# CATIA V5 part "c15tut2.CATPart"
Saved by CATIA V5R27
Part number: Part1
Bounding box of the stored display mesh (mm): x -53 to 53, y -20 to 21, z -12 to 52
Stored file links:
  E:\_Deepak\2017_Deepak\CATIA\Resources\Tutorial Files\Tutorials\c15_catia_v5_6r2016_tut\c15tut2.CATPart
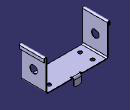
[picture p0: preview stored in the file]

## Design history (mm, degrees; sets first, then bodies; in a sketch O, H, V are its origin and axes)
SheetMetalParameters1: Thickness 1, BendRadius 2, KFactor 0.400515 {= log(min(100,max(20*SheetMetalParameters1.BendRadius,SheetMetalParameters1.Thickness)/SheetMetalParameters1.Thickness))/log(100)/2}, ReliefRadialLength 1, ReliefAxialLength 2, MinimumBendRadius 0
Body1 (main body)
  Sketch1 on xy-plane, origin (0, 0, 0), H (1, 0, 0), V (0, 1, 0)
    line L1 (50, 20) -> (50, -20)
    line L2 (50, -20) -> (-50, -20)
    line L3 (-50, -20) -> (-50, 20)
    line L4 (-50, 20) -> (50, 20)
    length L4 = 100
    length L1 = 40
    vertical: L1 V, L3 V
    horizontal: L2 H, L4 H
    equidistance: L1 L3 O, L2 L4 O
  Wall1: Thickness 1, Profile Sketch1
  Sketch2 on face of Wall1, origin (29.2419, -0.5458, 1), H (1, 0, 0), V (0, 1, 0)
    point P1 (-64.2419, -9.4542)
    reference projected line E1 (-79.2419, -19.4542) -> (-79.2419, 20.5458) from edge [face of Wall1 | face of Wall1]
    reference projected line E2 (20.7581, -19.4542) -> (-79.2419, -19.4542) from edge [face of Wall1 | face of Wall1]
    distance E1 P1 = 15
    distance E2 P1 = 10
  Hole1: placed by Sketch2, at (-35, -10, 1) direction (0, 0, -1), diameter 6, depth 10
  RectPattern1: of Hole1, direction 1 instances 2, spacing 70, along edge [face of Wall1 | face of Wall1] reversed, direction 2 instances 2, spacing 20, along edge [face of Wall1 | face of Wall1]
  Flange1: Angle 90, Length 50, Radius 2, KFacteur 0.400515 {= log(min(100,max(20*Flange1.Radius,SheetMetalParameters1.Thickness)/SheetMetalParameters1.Thickness))/log(100)/2}, Guide edge [face of Wall1 | face of Wall1]
  Flange2: Angle 90, Length 50, Radius 2, KFacteur 0.400515 {= log(min(100,max(20*Flange2.Radius,SheetMetalParameters1.Thickness)/SheetMetalParameters1.Thickness))/log(100)/2}, Guide edge [face of Wall1 | face of Wall1]
  Flange3: Angle 90, Length 5, Radius 1, KFacteur 0.325257 {= log(min(100,max(20*Flange3.Radius,SheetMetalParameters1.Thickness)/SheetMetalParameters1.Thickness))/log(100)/2}, Guide edge [face of Flange2 | face of Flange2]
  Flange4: Angle 90, Length 5, Radius 1, KFacteur 0.325257 {= log(min(100,max(20*Flange4.Radius,SheetMetalParameters1.Thickness)/SheetMetalParameters1.Thickness))/log(100)/2}, Guide edge [face of Flange1 | face of Flange1]
  Sketch3 on face of Flange1, origin (50, 0, 0), H (0, 1, 0), V (0, 0, 1)
    arc A1 centre (0, 25) radius 6 from (-1, 30.9161) to (1, 30.9161) ccw
    point P1 (0, 25)
    line L1 (-1, 30.9161) -> (-1, 29.9161)
    line L2 (-1, 29.9161) -> (1, 29.9161)
    line L3 (1, 29.9161) -> (1, 30.9161)
    radius A1 = 6
    distance H P1 = 25
    length L2 = 2
    distance V L1 = 1
    length L3 = 1
    coincidence: P1 V
    vertical: L1 V, L3 V
    horizontal: L2 H
  CutOut1: Direction Sketch3, EndLimit through (limit type 3), Orientation true, Profile Sketch3, StartLimit through (limit type 2)
  d_NewWallOnEdge1: NewWallOnEdge_Edge edge [face of Wall1 | face of Wall1], NewWallOnEdge_Length 13, NewWallOnEdge_HeightLimitOffset 0, NewWallOnEdge_WidthOffset1 -41, NewWallOnEdge_WidthOffset2 -41, NewWallOnEdge_Angle 90, NewWallOnEdge_BendRadiusValue 2 {= SheetMetalParameters1.BendRadius}, KFacteur 0.400515 {= log(min(100,max(20*d_NewWallOnEdge1.Radius,SheetMetalParameters1.Thickness)/SheetMetalParameters1.Thickness))/log(100)/2}
  Corner1: CornerRadius 3, CornerChamferEdges (edge [face of d_NewWallOnEdge1 | face of d_NewWallOnEdge1]; edge [face of d_NewWallOnEdge1 | face of d_NewWallOnEdge1])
